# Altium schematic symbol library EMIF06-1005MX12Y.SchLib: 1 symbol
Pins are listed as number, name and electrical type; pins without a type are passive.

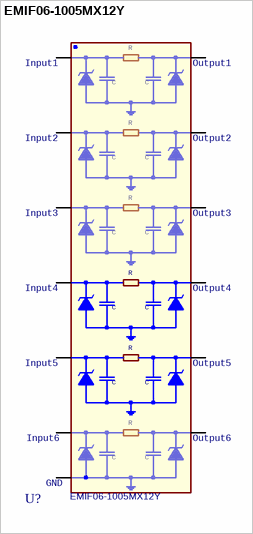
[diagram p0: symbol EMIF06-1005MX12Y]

## EMIF06-1005MX12Y
designator U?
footprint ST_QFN50P300X135X75-13L
pins: 1 Input1, 2 Input2, 3 Input3, 4 Input4, 5 Input5, 6 Input6, 7 Output6, 8 Output5, 9 Output4, 10 Output3, 11 Output2, 12 Output1, 13 GND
